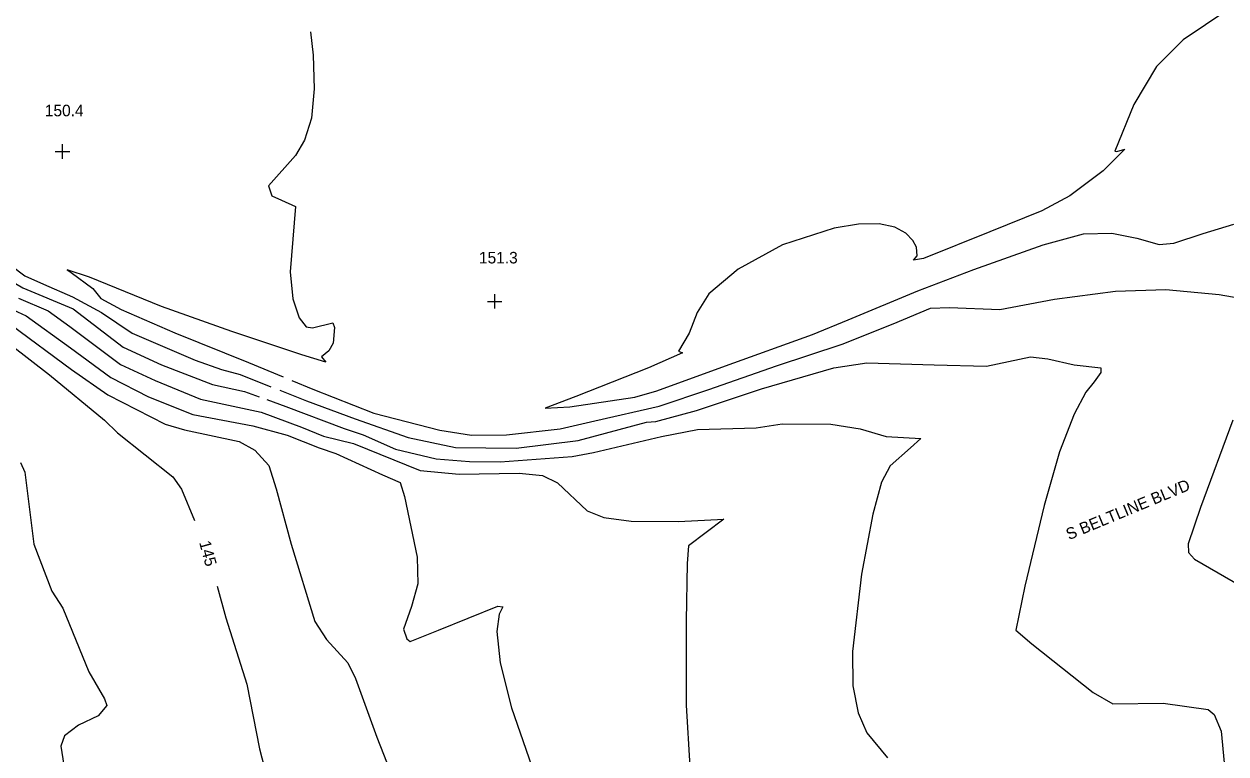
# Model space of a CAD drawing. Extents: x 1467615 to 2003689, y 770235 to 1108726.
# Drawn here: x 2002493.7 to 2002701.4, y 771446.8 to 771573 of the extents above; entities that cross this region are included whole.
import ezdxf

# ---------------------------------------------------------------- set-up
doc = ezdxf.new("R2010")
doc.units = 0
for name, color, linetype in [('RD_DTM_Major1', 7, 'Continuous'), ('RD_DTM_Major1_Lbl', 7, 'Continuous'), ('RD_DTM_Minor1', 7, 'Continuous'), ('RD_DTM_Spot_Elev', 7, 'Continuous'), ('RD_TX_Misc1', 7, 'Continuous')]:
    doc.layers.add(name, color=color, linetype=linetype)

msp = doc.modelspace()

# ---------------------------------------------------------------- linework, layer by layer
at = {"layer": 'RD_DTM_Major1'}
for points in [[(2002487.15, 771534.44), (2002493.84, 771529.43), (2002497.11, 771528), (2002502.11, 771525.82), (2002507.1, 771523.1), (2002512.38, 771519.55), (2002523.27, 771514.89), (2002527.83, 771513.27), (2002531.08, 771512.39), (2002536.38, 771510.29)], [(2002488.05, 771520.1), (2002498.11, 771512.37), (2002507.64, 771504.5), (2002509.87, 771502.34), (2002519.42, 771494.72), (2002520.94, 771492.56), (2002523.2, 771487.18)], [(2002537.92, 771509.68), (2002542.5, 771507.87), (2002550.93, 771504.72), (2002560.1, 771501.49), (2002568.3, 771499.8), (2002578.77, 771499.67), (2002589.45, 771500.99), (2002601.29, 771504.15), (2002602.9, 771504.26), (2002609.92, 771506.19), (2002621.12, 771509.92), (2002633.65, 771513.53), (2002639.33, 771514.41), (2002651.01, 771514.08), (2002660.05, 771513.82), (2002667.65, 771515.44), (2002670.62, 771515.13), (2002675.2, 771514.1), (2002679.77, 771513.53), (2002679.8, 771512.74), (2002678.62, 771511.16), (2002677.19, 771509.36), (2002675.17, 771505.57), (2002672.66, 771499.05), (2002669.98, 771489.78), (2002666.65, 771475.84), (2002665.1, 771468.22), (2002667.84, 771465.85), (2002678.44, 771457.46), (2002681.86, 771455.5), (2002690.58, 771455.62), (2002698.35, 771454.5), (2002699.39, 771453.66), (2002700.59, 771450.76), (2002701.12, 771445.31)], [(2002527.08, 771475.8), (2002528.58, 771470.37), (2002532.24, 771458.91), (2002534.42, 771447.72), (2002538.23, 771433.02)]]:
    msp.add_lwpolyline(points, dxfattribs=at)
at = {"layer": 'RD_DTM_Minor1'}
for points in [[(2002700.16, 771574.4), (2002697.84, 771572.82), (2002694, 771570.23), (2002689.38, 771565.62), (2002685.5, 771559.08), (2002682.18, 771551.01), (2002682.56, 771550.94), (2002683.95, 771551.33), (2002680.16, 771547.58), (2002674.45, 771543.26), (2002669.58, 771540.71), (2002660.61, 771537.06), (2002649.14, 771532.46), (2002647.43, 771532.16), (2002648.05, 771532.89), (2002647.94, 771534.4), (2002647.31, 771535.56), (2002646.1, 771536.8), (2002644.21, 771537.84), (2002641.49, 771538.42), (2002637.9, 771538.36), (2002633.69, 771537.67), (2002624.76, 771534.78), (2002617.1, 771530.58), (2002612.03, 771526.33), (2002610.01, 771523.11), (2002608.67, 771519.56), (2002606.8, 771516.44), (2002607.5, 771516.14), (2002601.65, 771513.55), (2002589.07, 771508.61), (2002583.76, 771506.58), (2002588.04, 771506.84), (2002599.28, 771508.48), (2002603.09, 771509.56), (2002614.91, 771513.89), (2002629.98, 771519.29), (2002636.15, 771521.82), (2002648.16, 771526.86), (2002657.82, 771530.56), (2002669.83, 771534.81), (2002676.78, 771536.69), (2002681.71, 771536.85), (2002685.99, 771535.97), (2002689.87, 771534.87), (2002692.42, 771535.09), (2002697.45, 771536.75), (2002702.75, 771538.4)], [(2002543.23, 771571.64), (2002543.7, 771567.56), (2002543.85, 771561.79), (2002543.37, 771556.7), (2002542.21, 771552.89), (2002540.64, 771550.24), (2002535.98, 771544.99), (2002536.54, 771543.28), (2002538.21, 771542.54), (2002540.62, 771541.44), (2002539.68, 771530.16), (2002540.17, 771525.48), (2002541.27, 771522.19), (2002542.45, 771520.61), (2002543.55, 771520.44), (2002547.1, 771521.34), (2002547.38, 771520.53), (2002547.15, 771517.82), (2002546.39, 771516.47), (2002545.13, 771515.46), (2002545.86, 771514.55), (2002541.72, 771515.8), (2002529.64, 771519.82), (2002517.47, 771524.15), (2002505.01, 771529.24), (2002501.15, 771530.5), (2002501.87, 771530.03), (2002505.63, 771527.26), (2002507.01, 771525.53), (2002510.49, 771523.64), (2002519.75, 771519.63), (2002532.5, 771514.47), (2002538.49, 771511.98)], [(2002464.69, 771553.86), (2002467.25, 771553.32), (2002471.17, 771551.61), (2002473.42, 771549.64), (2002476.76, 771545.04), (2002480.5, 771538.3), (2002484.73, 771533.84), (2002490.27, 771529.26), (2002493.53, 771527.37), (2002502.21, 771523.75), (2002510.83, 771517.13), (2002517.5, 771514.1), (2002526.29, 771510.65), (2002531.81, 771509.44), (2002534.36, 771508.53)], [(2002492.75, 771525.57), (2002497.88, 771523.43), (2002501.64, 771520.7), (2002510.41, 771514.13), (2002516.37, 771511.34), (2002524.23, 771508.13), (2002534.7, 771505.91), (2002541.67, 771503.29), (2002545.44, 771501.76), (2002550.63, 771500.49), (2002562.17, 771495.82), (2002568.9, 771495.16), (2002579.26, 771495.33), (2002583.33, 771494.97), (2002585.89, 771493.7), (2002591, 771488.84), (2002593.89, 771487.7), (2002598.63, 771487.04), (2002606.83, 771486.99), (2002614.66, 771487.4), (2002608.53, 771482.79), (2002608.31, 771479.74), (2002608.14, 771469.81), (2002608.12, 771455.24), (2002608.74, 771444.69)], [(2002539.98, 771511.36), (2002543.61, 771509.85), (2002554.15, 771505.73), (2002565.56, 771502.78), (2002571.06, 771501.94), (2002577.11, 771501.97), (2002586.36, 771502.99), (2002592.37, 771504.42), (2002603.48, 771506.91), (2002612.03, 771509.82), (2002623.73, 771513.92), (2002635.09, 771517.64), (2002643.89, 771521.18), (2002650.35, 771523.84), (2002653.64, 771523.96), (2002662.33, 771523.62), (2002671.79, 771525.4), (2002682.29, 771526.8), (2002691.03, 771527.07), (2002700.23, 771526.21), (2002709.14, 771524.67)], [(2002489.59, 771524.63), (2002494.09, 771522.53), (2002501.77, 771516.99), (2002508.69, 771511.88), (2002515.24, 771508.57), (2002522.9, 771505.48), (2002533.28, 771503.53), (2002539.17, 771501.91), (2002544.72, 771499.73), (2002547.59, 771498.74), (2002555.67, 771495.06), (2002558.7, 771493.75), (2002559.44, 771491.33), (2002561.66, 771480.83), (2002561.79, 771476.22), (2002560.68, 771472.31), (2002559.31, 771468.38), (2002559.84, 771466.71), (2002560.43, 771466.26), (2002565.33, 771468.24), (2002575.59, 771472.36), (2002576.44, 771472.26), (2002575.81, 771470.96), (2002575.41, 771467.97), (2002576.02, 771462.6), (2002577.93, 771454.8), (2002582.94, 771440.37)], [(2002491.52, 771520.97), (2002501.9, 771513.29), (2002508.22, 771508.87), (2002518.09, 771503.8), (2002521.43, 771502.86), (2002530.88, 771500.84), (2002533.61, 771499.3), (2002536.02, 771496.66), (2002537.27, 771492.65), (2002539.87, 771483.09), (2002543.97, 771469.71), (2002546.01, 771466.6), (2002549.65, 771462.56), (2002551, 771459.88), (2002554.67, 771449.76), (2002558.68, 771439.58)], [(2002535.67, 771508.06), (2002538.98, 771506.87), (2002549.01, 771503.09), (2002552.31, 771501.97), (2002557.91, 771499.49), (2002564.91, 771497.82), (2002570.69, 771497.38), (2002576, 771497.33), (2002588.43, 771498.23), (2002592.11, 771498.94), (2002603.86, 771501.68), (2002610.07, 771502.88), (2002620.22, 771503.19), (2002624.72, 771503.86), (2002633.11, 771503.84), (2002638.21, 771502.99), (2002642.71, 771501.68), (2002648.7, 771501.33), (2002646.91, 771499.71), (2002643.39, 771496.61), (2002641.89, 771493.77), (2002640.39, 771488.27), (2002638.43, 771477.92), (2002636.89, 771464.55), (2002636.95, 771458.58), (2002637.85, 771453.92), (2002639.36, 771450.47), (2002642.9, 771446.16)], [(2002702.57, 771504.5), (2002696.99, 771489.41), (2002694.85, 771483.17), (2002694.93, 771481.64), (2002695.96, 771480.49), (2002705.23, 771475.12)], [(2002493.1, 771497.18), (2002493.87, 771495.54), (2002495.43, 771483.08), (2002498.51, 771474.94), (2002500.44, 771472.01), (2002504.89, 771461), (2002507.65, 771456.33), (2002508.04, 771455.2), (2002506.54, 771453.4), (2002503.12, 771451.79), (2002500.7, 771449.98), (2002500.1, 771448.16), (2002500.57, 771444.92)]]:
    msp.add_lwpolyline(points, dxfattribs=at)
at = {"layer": 'RD_DTM_Spot_Elev'}
for p, q in [((2002499.11, 771550.94), (2002501.61, 771550.94)), ((2002500.36, 771549.69), (2002500.36, 771552.19)), ((2002575.05, 771523.79), (2002575.05, 771526.29)), ((2002573.8, 771525.04), (2002576.3, 771525.04))]:
    msp.add_line(p, q, dxfattribs=at)

# ---------------------------------------------------------------- texts
at = {"layer": 'RD_DTM_Major1_Lbl'}
msp.add_text('145', height=2, rotation=285.3749, dxfattribs=at).set_placement((2002523.96, 771483.38))
at = {"layer": 'RD_DTM_Spot_Elev'}
for s, p in [('150.4', (2002497.32, 771557.02)), ('151.3', (2002572.33, 771531.59))]:
    msp.add_text(s, height=2, dxfattribs=at).set_placement(p)
at = {"layer": 'RD_TX_Misc1'}
msp.add_text('S BELTLINE BLVD', height=2, rotation=22.5857, dxfattribs=at).set_placement((2002674.27, 771483.76))

doc.saveas('drawing.dxf')
